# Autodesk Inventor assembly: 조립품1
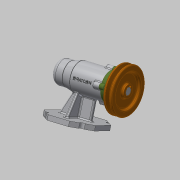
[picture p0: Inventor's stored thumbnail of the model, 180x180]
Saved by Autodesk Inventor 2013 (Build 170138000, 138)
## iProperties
Created: 2019-12
Part Number: 조립품1
Document SubType Name: Assembly
Designer: Administrator
Author: Administrator
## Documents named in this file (12)
- C:\Users\Administrator\Desktop\491204V1031\답안조립품.iam
- C:\Users\Administrator\Desktop\491204V1031\본체.ipt
- C:\Users\Administrator\Desktop\491204V1031\V벨트풀리.ipt
- C:\Users\Administrator\Desktop\491204V1031\멈춤나사 M3.ipt
- C:\Users\Administrator\Desktop\491204V1031\베어링 6004.ipt
- C:\Users\Administrator\Desktop\491204V1031\베어링 51202.ipt
- C:\Users\Administrator\Desktop\491204V1031\볼트 M4.ipt
- C:\Users\Administrator\Desktop\491204V1031\어댑터슬리브.ipt
- C:\Users\Administrator\Desktop\491204V1031\오일 실.ipt
- C:\Users\Administrator\Desktop\491204V1031\축.ipt
- C:\Users\Administrator\Desktop\491204V1031\커버.ipt
- C:\Users\Administrator\Desktop\491204V1031\키 5 x 5 x 16.ipt
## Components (1 placed, 1 different names)
1. V벨트풀리:1
